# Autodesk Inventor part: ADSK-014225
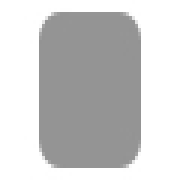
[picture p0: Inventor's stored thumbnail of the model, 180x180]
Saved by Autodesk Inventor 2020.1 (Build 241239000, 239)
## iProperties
Created: 2019-01
Part Number: ADSK-014225
Material: Stahl, weich
Document SubType Name: Modeling
Designer: lutzd
Language: de-DE
Size Designation: 5 x 39,384472 x 39,384472
Categories: <MemberInstance><Categories><Category DisplayName="Sonstige Bauteile" InternalName="5aa15e00-363f-49f2-933f-16f664388e3f" Mnemonic="OTHER"><Category DisplayName
Mass: 60.0398 g
Surface Area: 38.0412 cm^2
Volume: 7.64838 cm^3
Density: 7.85 g/cm^3
Appearance: Halbpoliert
IsCustomPart: 1
Title: Endcap
Author: lutzd
Revision Number: -
Dimensions: 39,4x39,4x5 mm
Mass: 0,06 kg
DocNumber: ADSK-014225
Folder: 01 - Themengebiete\Simplification\01 - Packaging machine\ADSK-014200\Frame\
VDS_Category: 3D Komponenten
VDS_NumSchm: Autodesk
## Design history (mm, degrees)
sketch "Sketch1"
  geometry: L1 (0, 20.175)-(0, -21.446); L2 (-20.203, 0)-(20.169, 0); L3 (-19.692, 19.692)-(19.692, 19.692); L4 (19.692, 19.692)-(19.692, -19.692); L5 (19.692, -19.692)-(-19.692, -19.692); L6 (-19.692, -19.692)-(-19.692, 19.692); 1 further point
  constraints: 12 end point, 2 horizontal, 2 parallel, 2 point on line, 1 perpendicular, 1 vertical
  dimensions: "d0" = 39.38447 distance between parallel lines of L5 L3 (= height); "d1" = 19.69224 distance between parallel lines of L2 L3 (= 0.5 x height); "d2" = 39.38447 distance between parallel lines of L6 L4 (= width); "d3" = 19.69224 distance between parallel lines of L6 L1 (= 0.5 x width)
extrude "Extrusion1" new body sketch "Sketch1" distance "d4" = 5 (= thickness); taper "d5" = 0 deg
fillet "Fillet1" dims "d6" = 5 (= fillet), "d7" = 0, "fillet" = 5 [user parameter; used in 1 equation term]
chamfer "Chamfer1" distance "d8" = 0 (computed from chamfer); stored, may be unused: second distance "d9" = 2, angle "d10" = 45 deg; dims "d11" = 0, "chamfer" = 0 [user parameter; used in 1 equation term]
body "Solid1"
other parameters: "thickness" = 5 [user parameter; used in 1 equation term], "width" = 39.38447 [user parameter; used in 2 equation terms], "height" = 39.38447 [user parameter; used in 2 equation terms]
